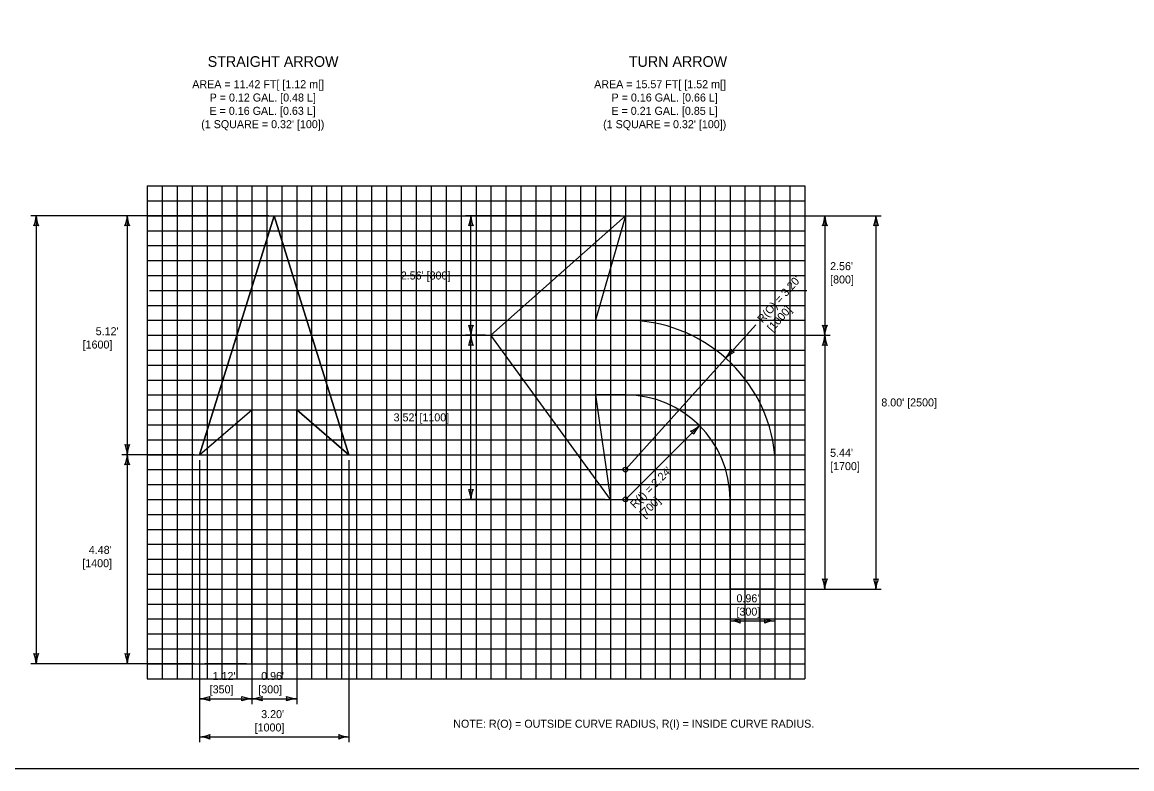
# Model space of a CAD drawing. Extents: x 49991.4 to 50021, y 49980.9 to 50011.4.
# Drawn here: x 50000.07 to 50008.39, y 49987.8 to 49993.4 of the extents above; entities that cross this region are included whole.
import ezdxf

# ---------------------------------------------------------------- set-up
doc = ezdxf.new("R2010")
doc.units = 0
for name, color, linetype in [('Level 1', 7, 'Continuous'), ('Level 2', 7, 'Continuous'), ('Level 3', 7, 'Continuous'), ('Level 9', 7, 'Continuous')]:
    doc.layers.add(name, color=color, linetype=linetype)

msp = doc.modelspace()

# ---------------------------------------------------------------- linework, layer by layer
at = {"layer": 'Level 1'}
for p, q in [((50001.403, 49990.155), (50001.963, 49991.947)), ((50001.963, 49991.947), (50002.523, 49990.155)), ((50003.587, 49991.051), (50004.595, 49991.947)), ((50004.595, 49991.947), (50004.371, 49991.163)), ((50004.371, 49991.163), (50004.595, 49991.163)), ((50004.483, 49989.819), (50003.587, 49991.051)), ((50004.595, 49990.603), (50004.371, 49990.603)), ((50004.371, 49990.603), (50004.483, 49989.819)), ((50001.403, 49990.155), (50001.795, 49990.491)), ((50001.795, 49988.587), (50001.795, 49990.491)), ((50002.131, 49988.587), (50002.131, 49990.491)), ((50002.523, 49990.155), (50002.131, 49990.491)), ((50005.715, 49990.155), (50005.715, 49989.147)), ((50005.379, 49989.147), (50005.379, 49989.819)), ((50005.715, 49989.147), (50005.379, 49989.147)), ((50001.795, 49988.587), (50002.131, 49988.587))]:
    msp.add_line(p, q, dxfattribs=at)
msp.add_lwpolyline([(49999.3835, 49998.9992), (50016.7501, 49998.9992), (50016.7501, 49987.7988), (49999.3835, 49987.7988)], close=True, dxfattribs=at)
msp.add_lwpolyline([(50002.523, 49990.155), (50001.963, 49991.947), (50001.403, 49990.155), (50001.795, 49990.491), (50001.795, 49988.587), (50002.131, 49988.587), (50002.131, 49990.491), (50002.523, 49990.155)], dxfattribs=at)
for centre, radius, start, end in [((50004.6006, 49990.043), 1.12, 5.73845, 90.28713), ((50004.595, 49989.819), 0.784, 360, 90)]:
    msp.add_arc(centre, radius, start, end, dxfattribs=at)
at = {"layer": 'Level 3'}
for p, q in [((50001.923, 49991.947), (50000.138, 49991.947)), ((50000.178, 49991.947), (50000.178, 49988.587)), ((50000.861, 49991.947), (50000.861, 49990.155)), ((50004.555, 49991.947), (50003.397, 49991.947)), ((50003.437, 49991.051), (50003.437, 49991.947)), ((50004.635, 49991.947), (50006.5129, 49991.947)), ((50006.089, 49991.947), (50006.089, 49991.051)), ((50006.4729, 49991.947), (50006.4729, 49989.147)), ((50005.5022, 49991.051), (50005.5727, 49991.1293)), ((50003.547, 49991.051), (50003.397, 49991.051)), ((50003.437, 49989.819), (50003.437, 49991.051)), ((50004.595, 49990.043), (50005.5022, 49991.051)), ((50005.1288, 49991.051), (50005.4622, 49991.051)), ((50005.5422, 49991.051), (50006.129, 49991.051)), ((50006.089, 49991.051), (50006.089, 49989.147)), ((50004.595, 49989.819), (50005.1493, 49990.3734)), ((50001.363, 49990.155), (50000.821, 49990.155)), ((50000.861, 49990.155), (50000.861, 49988.587)), ((50001.403, 49990.115), (50001.403, 49987.999)), ((50002.523, 49990.115), (50002.523, 49987.999)), ((50004.443, 49989.819), (50003.397, 49989.819)), ((50005.379, 49989.107), (50005.379, 49988.8679)), ((50005.715, 49989.107), (50005.715, 49988.8679)), ((50005.755, 49989.147), (50006.5129, 49989.147)), ((50005.379, 49988.9079), (50005.715, 49988.9079)), ((50001.363, 49988.587), (50000.138, 49988.587)), ((50001.755, 49988.587), (50001.443, 49988.587)), ((50001.795, 49988.547), (50001.795, 49988.285)), ((50002.131, 49988.547), (50002.131, 49988.285)), ((50001.403, 49988.325), (50001.795, 49988.325)), ((50001.795, 49988.325), (50002.131, 49988.325)), ((50001.403, 49988.039), (50002.523, 49988.039))]:
    msp.add_line(p, q, dxfattribs=at)
for centre in [(50004.595, 49990.043), (50004.595, 49989.819)]:
    msp.add_circle(centre, 0.0175, dxfattribs=at)
for centre, radius, start, end in [((49999.9558, 49991.9561), 0.2223, 337.45601, 357.63952), ((50000.4107, 49991.9585), 0.233, 182.82731, 202.07716), ((50000.6388, 49991.9561), 0.2223, 337.45601, 357.63952), ((50001.0937, 49991.9585), 0.233, 182.82731, 202.07716), ((50003.2148, 49991.9561), 0.2223, 337.45601, 357.63952), ((50003.6697, 49991.9585), 0.233, 182.82731, 202.07716), ((50005.8668, 49991.9561), 0.2223, 337.45601, 357.63952), ((50006.3217, 49991.9585), 0.233, 182.82731, 202.07716), ((50006.2507, 49991.9561), 0.2223, 337.45601, 357.63952), ((50006.7056, 49991.9585), 0.233, 182.82731, 202.07716), ((50000.178, 49991.8188), 0.0548, 72.13882, 107.86118), ((50000.861, 49991.8188), 0.0548, 72.13882, 107.86118), ((50003.437, 49991.8188), 0.0548, 72.13882, 107.86118), ((50006.089, 49991.8188), 0.0548, 72.13882, 107.86118), ((50006.4729, 49991.8188), 0.0548, 72.13882, 107.86118), ((50003.437, 49991.1792), 0.0548, 252.13882, 287.86118), ((50003.2043, 49991.0395), 0.233, 2.82731, 22.07716), ((50003.6591, 49991.0418), 0.2223, 157.45601, 177.63952), ((50006.089, 49991.1792), 0.0548, 252.13882, 287.86118), ((50005.8563, 49991.0395), 0.233, 2.82731, 22.07716), ((50006.3111, 49991.0418), 0.2223, 157.45601, 177.63952), ((50003.2148, 49991.0601), 0.2223, 337.45601, 357.63952), ((50003.6697, 49991.0625), 0.233, 182.82731, 202.07716), ((50005.8668, 49991.0601), 0.2223, 337.45601, 357.63952), ((50006.3217, 49991.0625), 0.233, 182.82731, 202.07716), ((50003.437, 49990.9228), 0.0548, 72.13882, 107.86118), ((50005.1661, 49991.0254), 0.233, 320.8401, 340.08995), ((50005.5057, 49990.7229), 0.2223, 115.4688, 135.65231), ((50005.4325, 49990.9736), 0.0548, 210.15161, 245.87397), ((50006.089, 49990.9228), 0.0548, 72.13882, 107.86118), ((50004.9987, 49990.5369), 0.2223, 292.45601, 312.63952), ((50005.0587, 49990.2827), 0.0548, 27.13882, 62.86118), ((50005.322, 49990.2169), 0.233, 137.82731, 157.07716), ((50000.861, 49990.2832), 0.0548, 252.13882, 287.86118), ((50000.6283, 49990.1435), 0.233, 2.82731, 22.07716), ((50001.0831, 49990.1458), 0.2223, 157.45601, 177.63952), ((50000.6388, 49990.1641), 0.2223, 337.45601, 357.63952), ((50000.861, 49990.0268), 0.0548, 72.13882, 107.86118), ((50001.0937, 49990.1665), 0.233, 182.82731, 202.07716), ((50003.437, 49989.9472), 0.0548, 252.13882, 287.86118), ((50003.2043, 49989.8075), 0.233, 2.82731, 22.07716), ((50003.6591, 49989.8098), 0.2223, 157.45601, 177.63952), ((50006.089, 49989.2752), 0.0548, 252.13882, 287.86118), ((50005.8563, 49989.1355), 0.233, 2.82731, 22.07716), ((50006.3111, 49989.1378), 0.2223, 157.45601, 177.63952), ((50006.4729, 49989.2752), 0.0548, 252.13882, 287.86118), ((50006.2402, 49989.1355), 0.233, 2.82731, 22.07716), ((50006.695, 49989.1378), 0.2223, 157.45601, 177.63952), ((50005.3675, 49989.1406), 0.233, 272.82731, 292.07716), ((50005.5072, 49988.9079), 0.0548, 162.13882, 197.86118), ((50005.7241, 49989.1301), 0.2223, 247.45601, 267.63952), ((50005.5868, 49988.9079), 0.0548, 342.13882, 17.86118), ((50005.3698, 49988.6858), 0.2223, 67.45601, 87.63952), ((50005.7265, 49988.6752), 0.233, 92.82731, 112.07716), ((50000.178, 49988.7152), 0.0548, 252.13882, 287.86118), ((49999.9452, 49988.5755), 0.233, 2.82731, 22.07716), ((50000.4001, 49988.5778), 0.2223, 157.45601, 177.63952), ((50000.861, 49988.7152), 0.0548, 252.13882, 287.86118), ((50000.6283, 49988.5755), 0.233, 2.82731, 22.07716), ((50001.0831, 49988.5778), 0.2223, 157.45601, 177.63952), ((50001.3915, 49988.5577), 0.233, 272.82731, 292.07716), ((50001.5312, 49988.325), 0.0548, 162.13882, 197.86118), ((50001.8041, 49988.5471), 0.2223, 247.45601, 267.63952), ((50001.6668, 49988.325), 0.0548, 342.13882, 17.86118), ((50001.7835, 49988.5577), 0.233, 272.82731, 292.07716), ((50001.9232, 49988.325), 0.0548, 162.13882, 197.86118), ((50002.1401, 49988.5471), 0.2223, 247.45601, 267.63952), ((50002.0028, 49988.325), 0.0548, 342.13882, 17.86118), ((50001.3938, 49988.1029), 0.2223, 67.45601, 87.63952), ((50001.8065, 49988.0923), 0.233, 92.82731, 112.07716), ((50001.7858, 49988.1029), 0.2223, 67.45601, 87.63952), ((50002.1425, 49988.0923), 0.233, 92.82731, 112.07716), ((50001.3915, 49988.2718), 0.233, 272.82731, 292.07716), ((50001.3938, 49987.8169), 0.2223, 67.45601, 87.63952), ((50001.5312, 49988.039), 0.0548, 162.13882, 197.86118), ((50002.5321, 49988.2612), 0.2223, 247.45601, 267.63952), ((50002.3948, 49988.039), 0.0548, 342.13882, 17.86118), ((50002.5345, 49987.8063), 0.233, 92.82731, 112.07716)]:
    msp.add_arc(centre, radius, start, end, dxfattribs=at)
at = {"layer": 'Level 9'}
for p, q in [((50001.011, 49992.171), (50005.939, 49992.171)), ((50001.011, 49992.171), (50001.011, 49988.475)), ((50001.123, 49992.171), (50001.123, 49988.475)), ((50001.235, 49992.171), (50001.235, 49988.475)), ((50001.347, 49992.171), (50001.347, 49988.475)), ((50001.459, 49992.171), (50001.459, 49988.475)), ((50001.571, 49992.171), (50001.571, 49988.475)), ((50001.683, 49992.171), (50001.683, 49988.475)), ((50001.795, 49992.171), (50001.795, 49988.475)), ((50001.907, 49992.171), (50001.907, 49988.475)), ((50002.019, 49992.171), (50002.019, 49988.475)), ((50002.131, 49992.171), (50002.131, 49988.475)), ((50002.243, 49992.171), (50002.243, 49988.475)), ((50002.355, 49992.171), (50002.355, 49988.475)), ((50002.467, 49992.171), (50002.467, 49988.475)), ((50002.579, 49992.171), (50002.579, 49988.475)), ((50002.691, 49992.171), (50002.691, 49988.475)), ((50002.803, 49992.171), (50002.803, 49988.475)), ((50002.915, 49992.171), (50002.915, 49988.475)), ((50003.027, 49992.171), (50003.027, 49988.475)), ((50003.139, 49992.171), (50003.139, 49988.475)), ((50003.251, 49992.171), (50003.251, 49988.475)), ((50003.363, 49992.171), (50003.363, 49988.475)), ((50003.475, 49992.171), (50003.475, 49988.475)), ((50003.587, 49992.171), (50003.587, 49988.475)), ((50003.699, 49992.171), (50003.699, 49988.475)), ((50003.811, 49992.171), (50003.811, 49988.475)), ((50003.923, 49992.171), (50003.923, 49988.475)), ((50004.035, 49992.171), (50004.035, 49988.475)), ((50004.147, 49992.171), (50004.147, 49988.475)), ((50004.259, 49992.171), (50004.259, 49988.475)), ((50004.371, 49992.171), (50004.371, 49988.475)), ((50004.483, 49992.171), (50004.483, 49988.475)), ((50004.595, 49992.171), (50004.595, 49988.475)), ((50004.707, 49992.171), (50004.707, 49988.475)), ((50004.819, 49992.171), (50004.819, 49988.475)), ((50004.931, 49992.171), (50004.931, 49988.475)), ((50005.043, 49992.171), (50005.043, 49988.475)), ((50005.155, 49992.171), (50005.155, 49988.475)), ((50005.267, 49992.171), (50005.267, 49988.475)), ((50005.379, 49992.171), (50005.379, 49988.475)), ((50005.491, 49992.171), (50005.491, 49988.475)), ((50005.603, 49992.171), (50005.603, 49988.475)), ((50005.715, 49992.171), (50005.715, 49988.475)), ((50005.827, 49992.171), (50005.827, 49988.475)), ((50005.939, 49992.171), (50005.939, 49988.475)), ((50001.011, 49992.059), (50005.939, 49992.059)), ((50001.011, 49991.947), (50005.939, 49991.947)), ((50001.011, 49991.835), (50005.939, 49991.835)), ((50001.011, 49991.723), (50005.939, 49991.723)), ((50001.011, 49991.611), (50005.939, 49991.611)), ((50001.011, 49991.499), (50005.939, 49991.499)), ((50001.0269, 49991.387), (50005.9549, 49991.387)), ((50001.011, 49991.275), (50005.939, 49991.275)), ((50001.011, 49991.163), (50005.939, 49991.163)), ((50001.011, 49991.051), (50005.939, 49991.051)), ((50001.011, 49990.939), (50005.939, 49990.939)), ((50001.011, 49990.827), (50005.939, 49990.827)), ((50001.011, 49990.715), (50005.939, 49990.715)), ((50001.011, 49990.603), (50005.939, 49990.603)), ((50001.011, 49990.491), (50005.939, 49990.491)), ((50001.011, 49990.379), (50005.939, 49990.379)), ((50001.011, 49990.267), (50005.939, 49990.267)), ((50001.011, 49990.155), (50005.939, 49990.155)), ((50001.011, 49990.043), (50005.939, 49990.043)), ((50001.011, 49989.931), (50005.939, 49989.931)), ((50001.011, 49989.819), (50005.939, 49989.819)), ((50001.011, 49989.707), (50005.939, 49989.707)), ((50001.011, 49989.595), (50005.939, 49989.595)), ((50001.011, 49989.483), (50005.939, 49989.483)), ((50001.011, 49989.371), (50005.939, 49989.371)), ((50001.011, 49989.259), (50005.939, 49989.259)), ((50001.011, 49989.147), (50005.939, 49989.147)), ((50001.011, 49989.035), (50005.939, 49989.035)), ((50001.011, 49988.923), (50005.939, 49988.923)), ((50001.011, 49988.811), (50005.939, 49988.811)), ((50001.011, 49988.699), (50005.939, 49988.699)), ((50001.011, 49988.587), (50005.939, 49988.587)), ((50001.011, 49988.475), (50005.939, 49988.475))]:
    msp.add_line(p, q, dxfattribs=at)

# ---------------------------------------------------------------- texts
at = {"layer": 'Level 2'}
for s, height, p in [('STRAIGHT ARROW', 0.08, (50001.4639, 49993.0639)), ('TURN ARROW', 0.08, (50004.6204, 49993.0639)), ('AREA = 11.42 FT[ [1.12 m[]', 0.06, (50001.3483, 49992.9039)), ('AREA = 15.57 FT[ [1.52 m[]', 0.06, (50004.3606, 49992.9039)), ('P = 0.12 GAL. [0.48 L]', 0.06, (50001.4786, 49992.8039)), ('P = 0.16 GAL. [0.66 L]', 0.06, (50004.491, 49992.8039)), ('E = 0.16 GAL. [0.63 L]', 0.06, (50001.4775, 49992.7039)), ('E = 0.21 GAL. [0.85 L]', 0.06, (50004.4898, 49992.7039)), ("(1 SQUARE = 0.32' [100])", 0.06, (50001.4154, 49992.6039)), ("(1 SQUARE = 0.32' [100])", 0.06, (50004.4277, 49992.6039)), ("2.56'", 0.06, (50006.129, 49991.539)), ("2.56' [800]", 0.06, (50002.9111, 49991.469)), ('[800]', 0.06, (50006.129, 49991.439)), ("5.12'", 0.06, (50000.6246, 49991.051)), ('[1600]', 0.06, (50000.5267, 49990.951)), ("8.00' [2500]", 0.06, (50006.5129, 49990.517)), ("3.52' [1100]", 0.06, (50002.8573, 49990.405)), ("5.44'", 0.06, (50006.129, 49990.139)), ('[1700]', 0.06, (50006.129, 49990.039)), ("4.48'", 0.06, (50000.573, 49989.411)), ('[1400]', 0.06, (50000.524, 49989.311)), ("0.96'", 0.06, (50005.4273, 49989.0479)), ('[300]', 0.06, (50005.4273, 49988.9479)), ("1.12'", 0.06, (50001.5009, 49988.465)), ("0.96'", 0.06, (50001.8649, 49988.465)), ('[350]', 0.06, (50001.4789, 49988.365)), ('[300]', 0.06, (50001.8429, 49988.365)), ("3.20'", 0.06, (50001.8649, 49988.179)), ('NOTE: R(O) = OUTSIDE CURVE RADIUS, R(I) = INSIDE CURVE RADIUS.', 0.06, (50003.3044, 49988.1071)), ('[1000]', 0.06, (50001.8159, 49988.079))]:
    msp.add_text(s, height=height, dxfattribs=at).set_placement(p)
for s, p in [("R(I) = 2.24'", (50004.6657, 49989.7483)), ('[700]', (50004.7364, 49989.6776))]:
    msp.add_text(s, height=0.06, rotation=45, dxfattribs=at).set_placement(p)
at = {"layer": 'Level 3'}
for s, p in [("R(O) = 3.20'", (50005.6217, 49991.139)), ('[1000]', (50005.696, 49991.0721))]:
    msp.add_text(s, height=0.06, rotation=48.01279, dxfattribs=at).set_placement(p)

doc.saveas('drawing.dxf')
